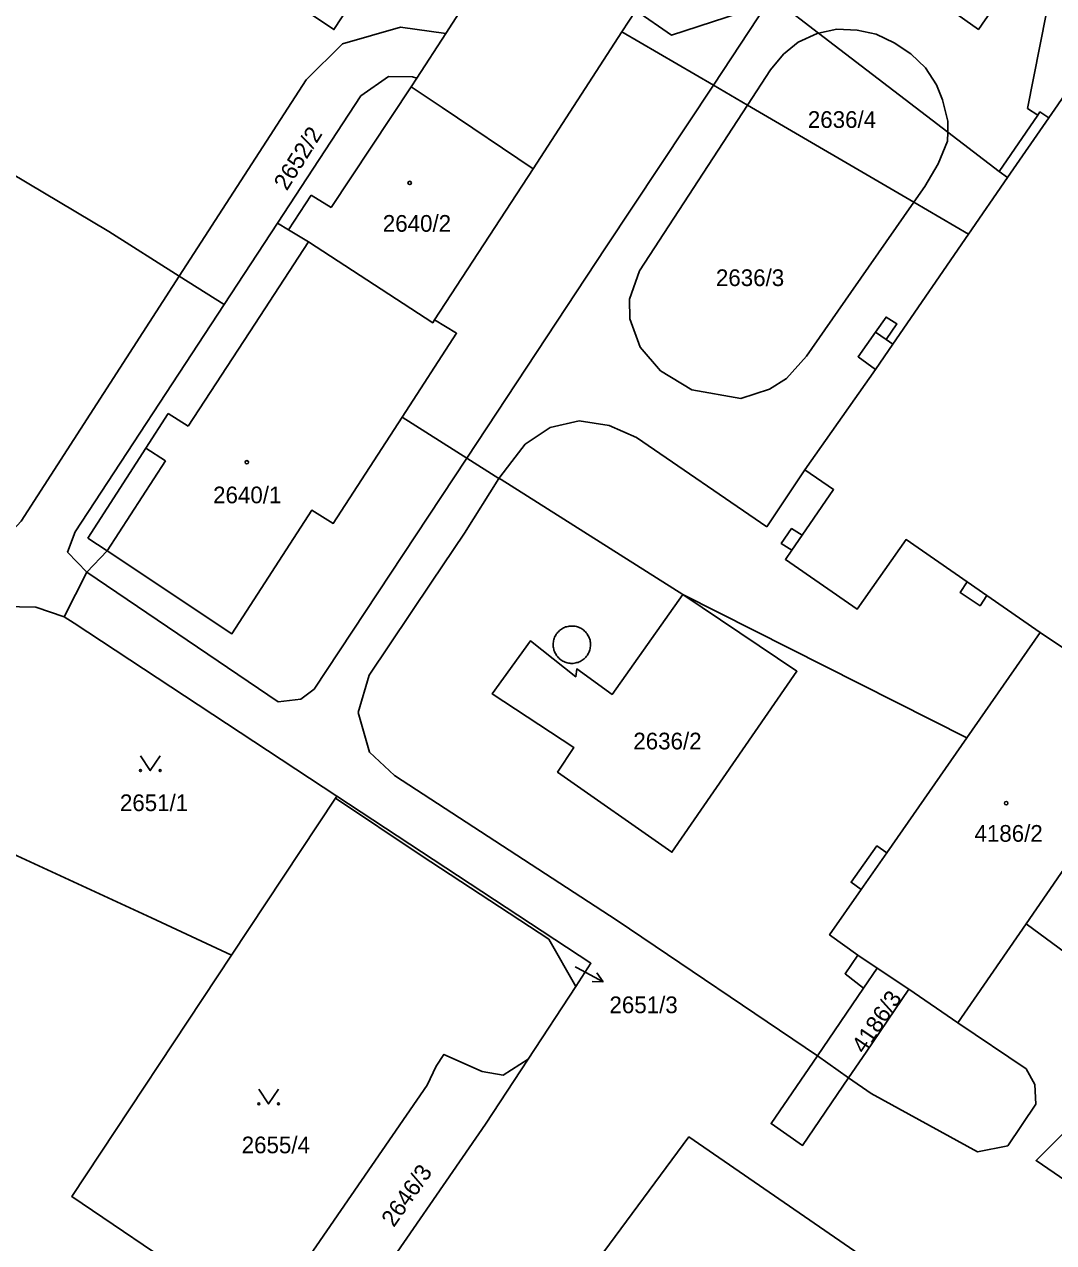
# Model space of a CAD drawing. Extents: x -527335 to -526256, y -1079142 to -1077836.
# Drawn here: x -527132.2 to -527027.3, y -1078723.7 to -1078599.7 of the extents above; entities that cross this region are included whole.
import ezdxf

# ---------------------------------------------------------------- set-up
doc = ezdxf.new("R2010")
doc.units = 0
for name, color, linetype in [('Hranice parcel', 7, 'Continuous'), ('Parcelní čísla', 7, 'Continuous'), ('Pop  PČ popisy', 7, 'Continuous'), ('Vnitřní kresba', 7, 'Continuous'), ('Značky budov', 7, 'Continuous'), ('Značky kultur', 7, 'Continuous')]:
    doc.layers.add(name, color=color, linetype=linetype)

msp = doc.modelspace()

# ---------------------------------------------------------------- linework, layer by layer
at = {"layer": 'Hranice parcel'}
for p, q in [((-527084.24, -1078592.92), (-527089.24, -1078600.63)), ((-527069.88, -1078598.28), (-527071.3, -1078600.46)), ((-527089.24, -1078600.63), (-527092.19, -1078605.19)), ((-527071.3, -1078600.46), (-527080.35, -1078614.41)), ((-527080.35, -1078614.41), (-527090.38, -1078629.79)), ((-527106.37, -1078619.93), (-527111.8, -1078628.22)), ((-527111.8, -1078628.22), (-527116.37, -1078625.34)), ((-527125.8, -1078655.47), (-527128.08, -1078659.99)), ((-527036.17, -1078672.32), (-527028.7, -1078661.6)), ((-527111.05, -1078694.45), (-527100.48, -1078678.48)), ((-527100.48, -1078678.48), (-527100.33, -1078678.25)), ((-527076, -1078697.64), (-527080.84, -1078705.04))]:
    msp.add_line(p, q, dxfattribs=at)
for points in [[(-527032.9, -1078614.69), (-527028.96, -1078608.95), (-527028.74, -1078608.62), (-527027.84, -1078609.21), (-527013.93, -1078589.06), (-527018.97, -1078585.47), (-527022.71, -1078582.8), (-527034.32, -1078599.25), (-527035, -1078600.21), (-527045.31, -1078592.89), (-527044.64, -1078591.95), (-527045.34, -1078591.68), (-527030.72, -1078570.54), (-527019.5, -1078578.37), (-527020.66, -1078580.03), (-527011.71, -1078586.28), (-527007.77, -1078580.59), (-526958.39, -1078614.81), (-526968.02, -1078629.02)], [(-527116.37, -1078625.34), (-527123.55, -1078620.8), (-527150.28, -1078604.87), (-527192.47, -1078579.74), (-527193.56, -1078579.08), (-527199.41, -1078575.6)], [(-527097.46, -1078584.88), (-527105.59, -1078596.9), (-527101.78, -1078599.46), (-527100.62, -1078600.24), (-527092.63, -1078588.02)], [(-527055.53, -1078597.34), (-527056.53, -1078597.66), (-527066.26, -1078600.79), (-527069.88, -1078598.28)], [(-527032.9, -1078614.69), (-527038.13, -1078610.68), (-527051.29, -1078600.6), (-527055.53, -1078597.34)], [(-527089.24, -1078600.63), (-527093.84, -1078599.97), (-527099.76, -1078601.69), (-527103.47, -1078605.35), (-527116.37, -1078625.34)], [(-527036.02, -1078621.06), (-527041.58, -1078617.81), (-527058.52, -1078607.92), (-527061.99, -1078605.89), (-527071.3, -1078600.46)], [(-527092.19, -1078605.19), (-527092.64, -1078605.04), (-527095.07, -1078605), (-527097.88, -1078606.99), (-527106.37, -1078619.93)], [(-527080.35, -1078614.41), (-527089.62, -1078608.18), (-527092.76, -1078606.07), (-527092.19, -1078605.19)], [(-527036.02, -1078621.06), (-527032.04, -1078615.3), (-527032.9, -1078614.69)], [(-527090.38, -1078629.79), (-527090.57, -1078630.08), (-527103.21, -1078621.85), (-527105.25, -1078620.61), (-527106.37, -1078619.93)], [(-527028.7, -1078661.6), (-527034.13, -1078657.85), (-527034.83, -1078658.88), (-527036.85, -1078657.54), (-527036.16, -1078656.44), (-527042.37, -1078652.15), (-527047.34, -1078659.21), (-527054.65, -1078654.16), (-527054.01, -1078653.23), (-527055.07, -1078652.54), (-527054.02, -1078651.02), (-527052.95, -1078651.7), (-527049.75, -1078647.05), (-527052.66, -1078645.04), (-527045.47, -1078634.82), (-527047.26, -1078633.54), (-527045.49, -1078631.04), (-527044.4, -1078629.5), (-527043.32, -1078630.17), (-527044.38, -1078631.79), (-527043.73, -1078632.24), (-527036.02, -1078621.06)], [(-527116.37, -1078625.34), (-527132.46, -1078650.27), (-527134.42, -1078652.38), (-527137.13, -1078653.92), (-527149.78, -1078655.77), (-527159.8, -1078657.78), (-527171.17, -1078661.31), (-527177.71, -1078664.84), (-527183.15, -1078668.47), (-527187.88, -1078671.32), (-527192.11, -1078672.93), (-527195.71, -1078673.39), (-527199.46, -1078672.73), (-527204.98, -1078670.57), (-527228.94, -1078656.95), (-527235.73, -1078654.01), (-527239.42, -1078653.58), (-527242.39, -1078654.19), (-527245.02, -1078654.86), (-527247.81, -1078654.99), (-527253.05, -1078652.95)], [(-527111.8, -1078628.22), (-527126.96, -1078651.34), (-527127.75, -1078653.43), (-527125.8, -1078655.47)], [(-527090.38, -1078629.79), (-527088.13, -1078631.14), (-527093.68, -1078639.69)], [(-527093.68, -1078639.69), (-527100.7, -1078650.5), (-527102.88, -1078649.16), (-527111.02, -1078661.73), (-527123.73, -1078653.3), (-527125.8, -1078655.47)], [(-527036.17, -1078672.32), (-527065.11, -1078657.74), (-527083.61, -1078646.04), (-527083.83, -1078645.91), (-527087.11, -1078643.84), (-527093.68, -1078639.69)], [(-527065.11, -1078657.74), (-527053.48, -1078665.54), (-527066.21, -1078683.97), (-527077.86, -1078675.81), (-527076.2, -1078673.3), (-527084.51, -1078667.86), (-527080.6, -1078662.44), (-527076, -1078666.1), (-527075.9, -1078665.3), (-527072.3, -1078667.9), (-527065.11, -1078657.74)], [(-527165.78, -1078664.86), (-527157.95, -1078662.5), (-527148.99, -1078660.76), (-527136.01, -1078658.93), (-527130.99, -1078659.02), (-527128.08, -1078659.99)], [(-527128.08, -1078659.99), (-527127.09, -1078660.65), (-527100.33, -1078678.25)], [(-527028.7, -1078661.6), (-527015.73, -1078670.3), (-527014.76, -1078670.99)], [(-527111.05, -1078694.45), (-527119.22, -1078690.63), (-527139.54, -1078681.28), (-527147.37, -1078677.43), (-527153.14, -1078673.82), (-527165.78, -1078664.86)], [(-527046.7, -1078697.8), (-527048.58, -1078696.34), (-527047.28, -1078694.45), (-527050.15, -1078692.37), (-527046.94, -1078687.77), (-527047.97, -1078687.02), (-527045.34, -1078683.32), (-527044.33, -1078684.02), (-527036.17, -1078672.32)], [(-527100.48, -1078678.48), (-527091.74, -1078684.3), (-527078.73, -1078692.83), (-527076, -1078697.64)], [(-527100.33, -1078678.25), (-527074.45, -1078695.27), (-527076, -1078697.64)], [(-527015.39, -1078682.81), (-527024.2, -1078695.62), (-527030.14, -1078691.25), (-527037.08, -1078701.34), (-527042.08, -1078697.91)], [(-527022.2, -1078722.85), (-527024.62, -1078721.48), (-527026.17, -1078719.51), (-527026.1, -1078717.42), (-527029.13, -1078715.35), (-527002.95, -1078689.07), (-527015.39, -1078682.81)], [(-527100.64, -1078733.75), (-527102.25, -1078735.96), (-527127.31, -1078719.02), (-527111.05, -1078694.45)], [(-527046.7, -1078697.8), (-527045.3, -1078695.78), (-527042.08, -1078697.91)], [(-527042.08, -1078697.91), (-527046.44, -1078704.32), (-527048.22, -1078706.92), (-527052.91, -1078713.81), (-527056.12, -1078711.58), (-527051.4, -1078704.68), (-527046.7, -1078697.8)], [(-527080.84, -1078705.04), (-527083.41, -1078706.65), (-527085.52, -1078706.27), (-527089.43, -1078704.54), (-527090.21, -1078705.74), (-527091.13, -1078707.66), (-527103.45, -1078725.55), (-527097.86, -1078729.26), (-527100.64, -1078733.75)], [(-527080.84, -1078705.04), (-527085.2, -1078711.65), (-527097.53, -1078729.48)], [(-527083.63, -1078738.83), (-527064.48, -1078712.94), (-527041.46, -1078728.79), (-527037.96, -1078731.19)]]:
    msp.add_lwpolyline(points, dxfattribs=at)
at = {"layer": 'Pop  PČ popisy'}
for p, q in [((-527076.07, -1078695.64), (-527075.87, -1078695.75)), ((-527075.87, -1078695.75), (-527073.22, -1078697.16)), ((-527073.22, -1078697.16), (-527073.87, -1078696.25)), ((-527073.22, -1078697.16), (-527074.34, -1078697.13))]:
    msp.add_line(p, q, dxfattribs=at)
at = {"layer": 'Vnitřní kresba'}
for p, q in [((-527061.99, -1078605.89), (-527056.53, -1078597.66)), ((-527028.09, -1078598.67), (-527030.01, -1078608.26)), ((-527053.36, -1078601.5), (-527051.41, -1078600.62)), ((-527051.41, -1078600.62), (-527051.29, -1078600.6)), ((-527051.29, -1078600.6), (-527049.42, -1078600.2)), ((-527049.42, -1078600.2), (-527047.35, -1078600.28)), ((-527047.35, -1078600.28), (-527045.41, -1078600.71)), ((-527045.41, -1078600.71), (-527043.57, -1078601.57)), ((-527054.84, -1078602.73), (-527053.36, -1078601.5)), ((-527043.57, -1078601.57), (-527041.87, -1078602.71)), ((-527056.18, -1078604.33), (-527054.84, -1078602.73)), ((-527041.87, -1078602.71), (-527040.4, -1078604.14)), ((-527056.18, -1078604.33), (-527058.52, -1078607.92)), ((-527040.4, -1078604.14), (-527039.27, -1078605.86)), ((-527039.27, -1078605.86), (-527038.67, -1078607.4)), ((-527092.76, -1078606.07), (-527100.9, -1078618.33)), ((-527072.91, -1078622.34), (-527061.99, -1078605.89)), ((-527058.52, -1078607.92), (-527069.52, -1078624.8)), ((-527038.67, -1078607.4), (-527038.11, -1078609.54)), ((-527030.01, -1078608.26), (-527028.96, -1078608.95)), ((-527038.11, -1078609.54), (-527038.13, -1078610.68)), ((-527032.04, -1078615.3), (-527027.84, -1078609.21)), ((-527038.13, -1078610.68), (-527038.14, -1078611.58)), ((-527038.14, -1078611.58), (-527039.1, -1078613.91)), ((-527039.1, -1078613.91), (-527040.45, -1078616.19)), ((-527040.45, -1078616.19), (-527041.58, -1078617.81)), ((-527102.93, -1078617.08), (-527105.25, -1078620.61)), ((-527100.9, -1078618.33), (-527102.93, -1078617.08)), ((-527047.98, -1078627), (-527041.58, -1078617.81)), ((-527103.21, -1078621.85), (-527108.68, -1078630.21)), ((-527087.11, -1078643.84), (-527072.91, -1078622.34)), ((-527069.52, -1078624.8), (-527070.53, -1078627.68)), ((-527070.53, -1078627.68), (-527070.5, -1078629.68)), ((-527052.51, -1078633.49), (-527047.98, -1078627)), ((-527115.47, -1078640.6), (-527108.68, -1078630.21)), ((-527070.5, -1078629.68), (-527069.45, -1078632.56)), ((-527044.38, -1078631.79), (-527045.49, -1078631.04)), ((-527069.45, -1078632.56), (-527067.37, -1078634.98)), ((-527043.73, -1078632.24), (-527045.47, -1078634.82)), ((-527054.54, -1078635.74), (-527052.51, -1078633.49)), ((-527067.37, -1078634.98), (-527064.19, -1078636.89)), ((-527059.19, -1078637.78), (-527056.26, -1078636.85)), ((-527056.26, -1078636.85), (-527054.54, -1078635.74)), ((-527064.19, -1078636.89), (-527059.19, -1078637.78)), ((-527119.77, -1078642.84), (-527117.5, -1078639.31)), ((-527117.5, -1078639.31), (-527115.47, -1078640.6)), ((-527078.62, -1078640.73), (-527075.65, -1078640.07)), ((-527075.65, -1078640.07), (-527072.61, -1078640.52)), ((-527072.61, -1078640.52), (-527069.83, -1078641.75)), ((-527081.14, -1078642.44), (-527078.62, -1078640.73)), ((-527069.83, -1078641.75), (-527056.54, -1078650.84)), ((-527125.67, -1078652.01), (-527119.77, -1078642.84)), ((-527117.77, -1078644.13), (-527119.77, -1078642.84)), ((-527082.52, -1078644.19), (-527081.14, -1078642.44)), ((-527117.77, -1078644.13), (-527123.73, -1078653.3)), ((-527102.65, -1078667.38), (-527087.11, -1078643.84)), ((-527083.83, -1078645.91), (-527082.52, -1078644.19)), ((-527056.54, -1078650.84), (-527052.66, -1078645.04)), ((-527087.34, -1078651.48), (-527083.83, -1078645.91)), ((-527090.69, -1078656.47), (-527087.34, -1078651.48)), ((-527052.95, -1078651.7), (-527054.01, -1078653.23)), ((-527123.73, -1078653.3), (-527125.67, -1078652.01)), ((-527106.3, -1078668.65), (-527125.8, -1078655.47)), ((-527097.03, -1078665.93), (-527090.69, -1078656.47)), ((-527034.13, -1078657.85), (-527036.16, -1078656.44)), ((-527098.17, -1078669.75), (-527097.03, -1078665.93)), ((-527102.65, -1078667.38), (-527104, -1078668.4)), ((-527104, -1078668.4), (-527106.3, -1078668.65)), ((-527097, -1078673.79), (-527098.17, -1078669.75)), ((-527015.73, -1078670.3), (-527030.14, -1078691.25)), ((-527094.47, -1078676.17), (-527097, -1078673.79)), ((-527071.8, -1078690.93), (-527094.47, -1078676.17)), ((-527046.94, -1078687.77), (-527044.33, -1078684.02)), ((-527051.4, -1078704.68), (-527071.8, -1078690.93)), ((-527045.3, -1078695.78), (-527047.28, -1078694.45)), ((-527030.14, -1078706.02), (-527037.08, -1078701.34)), ((-527048.22, -1078706.92), (-527051.4, -1078704.68)), ((-527029.26, -1078707.61), (-527030.14, -1078706.02)), ((-527048.22, -1078706.92), (-527045.92, -1078708.54)), ((-527045.92, -1078708.54), (-527035.09, -1078714.45)), ((-527029.16, -1078709.61), (-527029.26, -1078707.61)), ((-527032, -1078713.85), (-527029.16, -1078709.61)), ((-527035.09, -1078714.45), (-527032, -1078713.85))]:
    msp.add_line(p, q, dxfattribs=at)
for points in [[(-527077.79, -1078664.14), (-527077.87, -1078664.05), (-527077.95, -1078663.95), (-527078.01, -1078663.85), (-527078.07, -1078663.75), (-527078.13, -1078663.64), (-527078.18, -1078663.52), (-527078.22, -1078663.41), (-527078.25, -1078663.29), (-527078.27, -1078663.17), (-527078.29, -1078663.05), (-527078.3, -1078662.93), (-527078.3, -1078662.81), (-527078.3, -1078662.69), (-527078.28, -1078662.56), (-527078.26, -1078662.44), (-527078.23, -1078662.32), (-527078.2, -1078662.21), (-527078.15, -1078662.09), (-527078.1, -1078661.99), (-527078.04, -1078661.88), (-527077.98, -1078661.77), (-527077.91, -1078661.68), (-527077.83, -1078661.58), (-527077.74, -1078661.49), (-527077.66, -1078661.41), (-527077.56, -1078661.33), (-527077.46, -1078661.26), (-527077.36, -1078661.2), (-527077.25, -1078661.14), (-527077.14, -1078661.09), (-527077.03, -1078661.04), (-527076.91, -1078661.01), (-527076.79, -1078660.98), (-527076.67, -1078660.96), (-527076.55, -1078660.94), (-527076.43, -1078660.94), (-527076.31, -1078660.94), (-527076.18, -1078660.95), (-527076.06, -1078660.97), (-527075.94, -1078660.99), (-527075.83, -1078661.02), (-527075.71, -1078661.07), (-527075.6, -1078661.11), (-527075.49, -1078661.17), (-527075.39, -1078661.23), (-527075.28, -1078661.3), (-527075.19, -1078661.37), (-527075.1, -1078661.45), (-527075.01, -1078661.54)], [(-527075.01, -1078661.54), (-527074.93, -1078661.63), (-527074.85, -1078661.73), (-527074.79, -1078661.83), (-527074.73, -1078661.94), (-527074.67, -1078662.04), (-527074.62, -1078662.16), (-527074.58, -1078662.27), (-527074.55, -1078662.39), (-527074.53, -1078662.51), (-527074.51, -1078662.63), (-527074.5, -1078662.75), (-527074.5, -1078662.87), (-527074.5, -1078663), (-527074.52, -1078663.12), (-527074.54, -1078663.24), (-527074.57, -1078663.35), (-527074.6, -1078663.47), (-527074.65, -1078663.58), (-527074.7, -1078663.7), (-527074.76, -1078663.8), (-527074.82, -1078663.91), (-527074.9, -1078664.01), (-527074.97, -1078664.1), (-527075.06, -1078664.19), (-527075.15, -1078664.27), (-527075.24, -1078664.35), (-527075.34, -1078664.42), (-527075.44, -1078664.48), (-527075.55, -1078664.54), (-527075.66, -1078664.59), (-527075.77, -1078664.64), (-527075.89, -1078664.67), (-527076.01, -1078664.7), (-527076.13, -1078664.72), (-527076.25, -1078664.74), (-527076.37, -1078664.74), (-527076.49, -1078664.74), (-527076.62, -1078664.73), (-527076.74, -1078664.71), (-527076.86, -1078664.69), (-527076.97, -1078664.66), (-527077.09, -1078664.61), (-527077.2, -1078664.57), (-527077.31, -1078664.51), (-527077.42, -1078664.45), (-527077.52, -1078664.38), (-527077.61, -1078664.31), (-527077.7, -1078664.23), (-527077.79, -1078664.14)]]:
    msp.add_lwpolyline(points, dxfattribs=at)
at = {"layer": 'Značky budov'}
for centre in [(-527092.91, -1078615.84), (-527109.5, -1078644.27), (-527032.17, -1078678.97)]:
    msp.add_circle(centre, 0.175, dxfattribs=at)
at = {"layer": 'Značky kultur'}
for points in [[(-527120.33, -1078674.15), (-527119.33, -1078675.65), (-527118.33, -1078674.15)], [(-527108.28, -1078708.08), (-527107.28, -1078709.58), (-527106.28, -1078708.08)]]:
    msp.add_lwpolyline(points, dxfattribs=at)
for centre in [(-527120.33, -1078675.65), (-527118.33, -1078675.65), (-527108.28, -1078709.58), (-527106.28, -1078709.58)]:
    msp.add_circle(centre, 0.1, dxfattribs=at)

# ---------------------------------------------------------------- texts
at = {"layer": 'Parcelní čísla'}
for s, p in [('2636/4', (-527052.37, -1078610.24)), ('2640/2', (-527095.65, -1078620.81)), ('2636/3', (-527061.73, -1078626.34)), ('2640/1', (-527112.93, -1078648.45)), ('2636/2', (-527070.14, -1078673.5)), ('2651/1', (-527122.42, -1078679.78)), ('4186/2', (-527035.4, -1078682.9)), ('2651/3', (-527072.57, -1078700.35)), ('2655/4', (-527110.02, -1078714.61))]:
    msp.add_text(s, height=1.7, dxfattribs=at).set_placement(p)
for s, rotation, p in [('2652/2', 58, (-527105.42, -1078616.72)), ('4186/3', 56, (-527046.62, -1078704.57)), ('2646/3', 55, (-527094.53, -1078722.22))]:
    msp.add_text(s, height=1.7, rotation=rotation, dxfattribs=at).set_placement(p)

doc.saveas('drawing.dxf')
